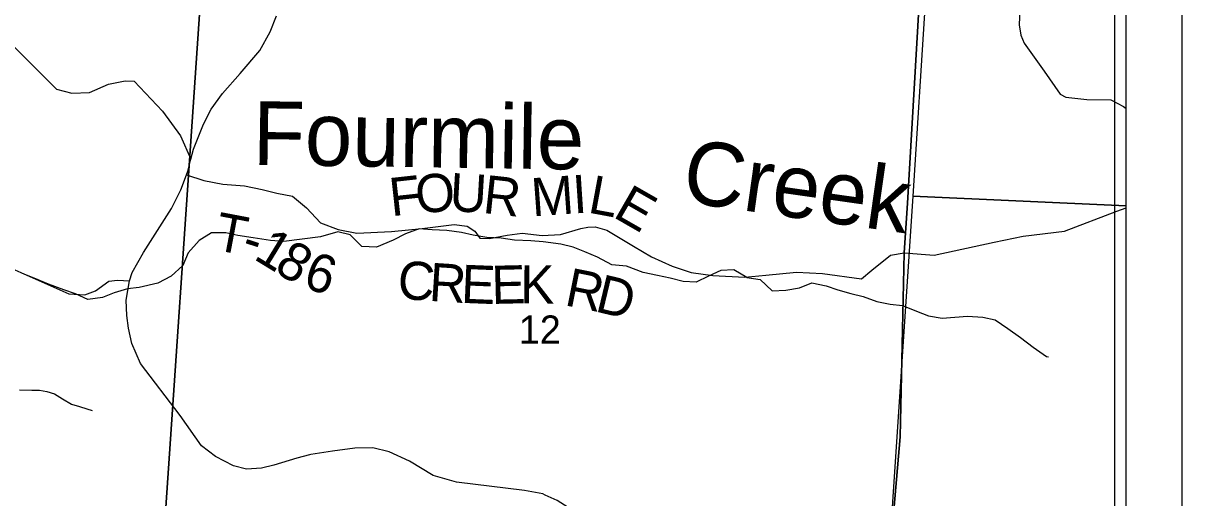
# Model space of a CAD drawing. Extents: x 0 to 34, y 0 to 22.
# Drawn here: x 7.778 to 9.5, y 19.094 to 19.8 of the extents above; entities that cross this region are included whole.
import ezdxf

# ---------------------------------------------------------------- set-up
doc = ezdxf.new("R2010")
doc.units = 0
for name, color, linetype in [('GM_X_County', 7, 'Continuous'), ('GM_X_County_Road', 7, 'Continuous'), ('GM_X_Minor_River', 7, 'Continuous'), ('GM_X_Minor_River_Text', 7, 'Continuous'), ('GM_X_Section', 7, 'Continuous'), ('GM_X_Section_Text', 7, 'Continuous'), ('GM_X_State_Route', 7, 'Continuous'), ('GM_X_Township', 7, 'Continuous'), ('GM_X_Township_Road', 7, 'Continuous'), ('GM_X_Township_Road_Text', 7, 'Continuous'), ('GM_X_Township_ROW', 7, 'Continuous'), ('SH_Data', 7, 'Continuous')]:
    doc.layers.add(name, color=color, linetype=linetype)

msp = doc.modelspace()

# ---------------------------------------------------------------- linework, layer by layer
at = {"layer": 'GM_X_County'}
msp.add_lwpolyline([(9.4175, 16.6203), (9.4175, 20.9), (2.6175, 20.9), (2.6175, 15.1694)], dxfattribs=at)
at = {"layer": 'GM_X_County_Road'}
for points in [[(9.2655, 19.8738), (9.2595, 19.8317), (9.2584, 19.7972), (9.2607, 19.7816), (9.2657, 19.7699), (9.2956, 19.7282), (9.3191, 19.6941), (9.3275, 19.6895), (9.3589, 19.6862), (9.3945, 19.6855), (9.4131, 19.6757), (9.4175, 19.6725)], [(7.6403, 19.4086), (7.6564, 19.4261), (7.6738, 19.4429), (7.6937, 19.4503), (7.7109, 19.4522), (7.738, 19.4446), (7.8456, 19.397), (7.8695, 19.3955), (7.885, 19.4016), (7.9051, 19.4157), (7.918, 19.4176), (7.9357, 19.4163)]]:
    msp.add_lwpolyline(points, dxfattribs=at)
at = {"layer": 'GM_X_Minor_River'}
for points in [[(8.8533, 19.4212), (8.8342, 19.4326), (8.8145, 19.4319), (8.7963, 19.4235), (8.7781, 19.4144), (8.7585, 19.4152), (8.7395, 19.4205), (8.7206, 19.4244), (8.6994, 19.4289), (8.6745, 19.438), (8.6525, 19.4403), (8.6313, 19.4517), (8.6124, 19.4593), (8.595, 19.4662), (8.5769, 19.4707), (8.5504, 19.4745), (8.5322, 19.4761), (8.508, 19.4769), (8.4883, 19.4799), (8.4671, 19.4807), (8.4467, 19.4845), (8.4293, 19.4883), (8.4073, 19.4913), (8.3854, 19.4921), (8.3665, 19.4936), (8.346, 19.4861), (8.3278, 19.477), (8.3028, 19.4664), (8.2809, 19.4672), (8.2635, 19.4846), (8.2453, 19.4892), (8.2196, 19.4816), (8.1651, 19.4748), (8.1454, 19.4764), (8.1196, 19.4802), (8.0969, 19.484), (8.0788, 19.4878), (8.0576, 19.4878), (8.0394, 19.4764), (8.0227, 19.4582), (8.0151, 19.4393), (7.9977, 19.4234), (7.978, 19.4128), (7.95, 19.4067), (7.9325, 19.4045), (7.9128, 19.3984), (7.8954, 19.3916), (7.8735, 19.3886), (7.8553, 19.3969), (7.8379, 19.403), (7.8152, 19.4114), (7.794, 19.4205), (7.7766, 19.4273)], [(8.8533, 19.4212), (8.8734, 19.4182), (8.8908, 19.4015), (8.9113, 19.4023), (8.9317, 19.4061), (8.9499, 19.4136), (8.9711, 19.4091), (8.9885, 19.403), (9.0082, 19.3977), (9.0263, 19.3932), (9.0468, 19.3856), (9.0665, 19.3819), (9.0846, 19.3796), (9.1058, 19.3712), (9.1232, 19.3644), (9.1437, 19.3606), (9.1815, 19.3637), (9.2042, 19.3622), (9.2224, 19.3584), (9.2413, 19.3455), (9.2602, 19.3319), (9.2791, 19.3175), (9.2988, 19.3038), (9.3019, 19.3031)], [(7.7721, 19.2543), (7.7903, 19.2536), (7.802, 19.254), (7.813, 19.2517), (7.824, 19.2483), (7.8361, 19.2407), (7.8497, 19.2331), (7.8615, 19.2297), (7.8721, 19.226), (7.8804, 19.2237)]]:
    msp.add_lwpolyline(points, dxfattribs=at)
at = {"layer": 'GM_X_Section'}
for p, q in [((9.4175, 19.5279), (9.4175, 20.557)), ((9.4175, 18.4879), (9.4175, 19.5279))]:
    msp.add_line(p, q, dxfattribs=at)
for points in [[(9.4175, 20.557), (9.1679, 20.569), (9.1186, 19.8297), (9.0999, 19.5424), (9.4175, 19.5279)], [(9.4175, 19.5279), (9.0999, 19.5424), (9.0522, 18.819), (9.0316, 18.5064), (9.4175, 18.4879)]]:
    msp.add_lwpolyline(points, dxfattribs=at)
for points in [[(6.9795, 19.9566), (8.0453, 19.8934), (7.9764, 18.8836), (6.9173, 18.9472)], [(8.0453, 19.8934), (9.1186, 19.8297), (9.0999, 19.5424), (9.0522, 18.819), (7.9764, 18.8836)]]:
    msp.add_lwpolyline(points, close=True, dxfattribs=at)
at = {"layer": 'GM_X_State_Route'}
for points in [[(8.2035, 19.1574), (8.1843, 19.1526), (8.1504, 19.1424), (8.132, 19.1375), (8.1097, 19.1365), (8.0903, 19.1411), (8.0636, 19.1553), (8.0429, 19.171), (8.011, 19.2161), (7.9518, 19.2934), (7.9393, 19.3233), (7.9341, 19.346), (7.9318, 19.3647), (7.9309, 19.3875), (7.9357, 19.4163), (7.9398, 19.4287), (7.9564, 19.4583), (7.9982, 19.524), (8.0121, 19.5518), (8.0203, 19.5741), (8.0223, 19.5796), (8.027, 19.5973), (8.031, 19.612), (8.0455, 19.6492), (8.0571, 19.6717), (8.0739, 19.6952), (8.1004, 19.7246), (8.1293, 19.7588), (8.1447, 19.7869), (8.1541, 19.8107)], [(8.5535, 19.0977), (8.5499, 19.0994), (8.523, 19.1046), (8.422, 19.1168), (8.3872, 19.127), (8.352, 19.1483), (8.3217, 19.1622), (8.2974, 19.1681), (8.2708, 19.1677), (8.2376, 19.1631), (8.2054, 19.1579), (8.2035, 19.1574)], [(8.6885, 18.8462), (8.6848, 18.8562), (8.6744, 18.9234), (8.6685, 18.9644), (8.6637, 18.9815), (8.6541, 19.0078), (8.6418, 19.0308), (8.6321, 19.0412), (8.614, 19.061), (8.5934, 19.0759), (8.5713, 19.0895), (8.5535, 19.0977)]]:
    msp.add_lwpolyline(points, dxfattribs=at)
at = {"layer": 'GM_X_Township'}
for points in [[(9.0224, 18.4988), (9.0811, 19.1844), (9.0872, 19.4578), (9.0922, 19.532), (9.1089, 19.821), (9.1308, 20.1394), (9.1474, 20.3825), (9.1598, 20.5629), (9.1905, 20.8388), (9.1263, 20.8428), (8.8507, 20.8503), (8.6801, 20.8642), (8.3786, 20.8887), (8.2133, 20.9)], [(9.195, 20.9), (9.1939, 20.8823), (9.1905, 20.8388), (9.1598, 20.5629), (9.1474, 20.3825), (9.1308, 20.1394), (9.1089, 19.821), (9.0922, 19.532), (9.0872, 19.4578), (9.0811, 19.1844), (9.0224, 18.4988)], [(9.4175, 16.6203), (9.4175, 20.9), (9.195, 20.9)]]:
    msp.add_lwpolyline(points, dxfattribs=at)
at = {"layer": 'GM_X_Township_Road'}
for points in [[(7.4061, 20.1217), (7.8271, 19.7012), (7.8498, 19.6955), (7.876, 19.6967), (7.9045, 19.7087), (7.9293, 19.714), (7.9426, 19.7134), (7.9847, 19.6686), (8.0115, 19.6318), (8.027, 19.5973)], [(8.0203, 19.5741), (8.0462, 19.5657), (8.0743, 19.5603), (8.1064, 19.5577), (8.1328, 19.5524)], [(8.1328, 19.5524), (8.1331, 19.5523), (8.1545, 19.547), (8.1779, 19.5423), (8.1986, 19.5249), (8.2195, 19.5025), (8.2461, 19.4927), (8.2734, 19.4871), (8.3253, 19.4895), (8.3708, 19.4941), (8.4181, 19.5003), (8.4375, 19.4977), (8.4488, 19.4901), (8.4565, 19.4799), (8.4709, 19.4795), (8.497, 19.4845), (8.5194, 19.4872), (8.5493, 19.4839), (8.5766, 19.4851), (8.6065, 19.4943), (8.6171, 19.4962), (8.6281, 19.4966), (8.6452, 19.4917), (8.6847, 19.4679), (8.7116, 19.452), (8.7424, 19.4384), (8.7704, 19.429), (8.8027, 19.4245), (8.8504, 19.4216), (8.8816, 19.4247)]]:
    msp.add_lwpolyline(points, dxfattribs=at)
at = {"layer": 'GM_X_Township_ROW'}
for points in [[(9.0393, 19.4321), (9.0668, 19.4546), (9.0872, 19.4578), (9.132, 19.4544), (9.2212, 19.4737), (9.2641, 19.4827), (9.3257, 19.4903), (9.4032, 19.5201), (9.4175, 19.5247)], [(8.8816, 19.4247), (8.927, 19.4293), (8.9658, 19.4271), (9.0237, 19.4194), (9.0393, 19.4321)]]:
    msp.add_lwpolyline(points, dxfattribs=at)
at = {"layer": 'SH_Data'}
for p, q in [((9.5, 21), (9.5, 14)), ((9.4, 20.9), (9.4, 14.1))]:
    msp.add_line(p, q, dxfattribs=at)

# ---------------------------------------------------------------- texts
at = {"layer": 'GM_X_Minor_River_Text'}
for s, rotation, p in [('Fourmile', 359.1567, (8.1185, 19.589)), ('Creek', 351.9245, (8.7545, 19.5344))]:
    msp.add_text(s, height=0.09469, rotation=rotation, dxfattribs=at).set_placement(p)
at = {"layer": 'GM_X_Section_Text'}
msp.add_text('12', height=0.04186, rotation=0, dxfattribs=at).set_placement((8.5145, 19.323))
at = {"layer": 'GM_X_Township_Road_Text'}
for s, rotation, p in [('F', 6.2734, (8.325, 19.5123)), ('O', 4.4026, (8.3626, 19.5165)), ('U', 356.7575, (8.4105, 19.5203)), ('R', 353.7537, (8.4596, 19.5175)), ('M', 4.0931, (8.5347, 19.5121)), ('I', 3.7536, (8.5961, 19.5165)), ('L', 349.4843, (8.6156, 19.5182)), ('E', 330.2075, (8.6527, 19.5122)), ('T', 349.2469, (8.0596, 19.463)), ('1', 328.6047, (8.1185, 19.4497)), ('-', 341.7817, (8.0995, 19.4555)), ('8', 328.8213, (8.1486, 19.4313)), ('6', 342.1011, (8.1916, 19.4072)), ('C', 356.0339, (8.3329, 19.39)), ('R', 356.3489, (8.3798, 19.3867)), ('E', 357.6936, (8.4279, 19.3837)), ('E', 1.3733, (8.4743, 19.3819)), ('K', 359.6216, (8.5163, 19.3829)), ('R', 348.7119, (8.5808, 19.3803)), ('D', 346.5018, (8.626, 19.3713))]:
    msp.add_text(s, height=0.0568, rotation=rotation, dxfattribs=at).set_placement(p)

doc.saveas('drawing.dxf')
